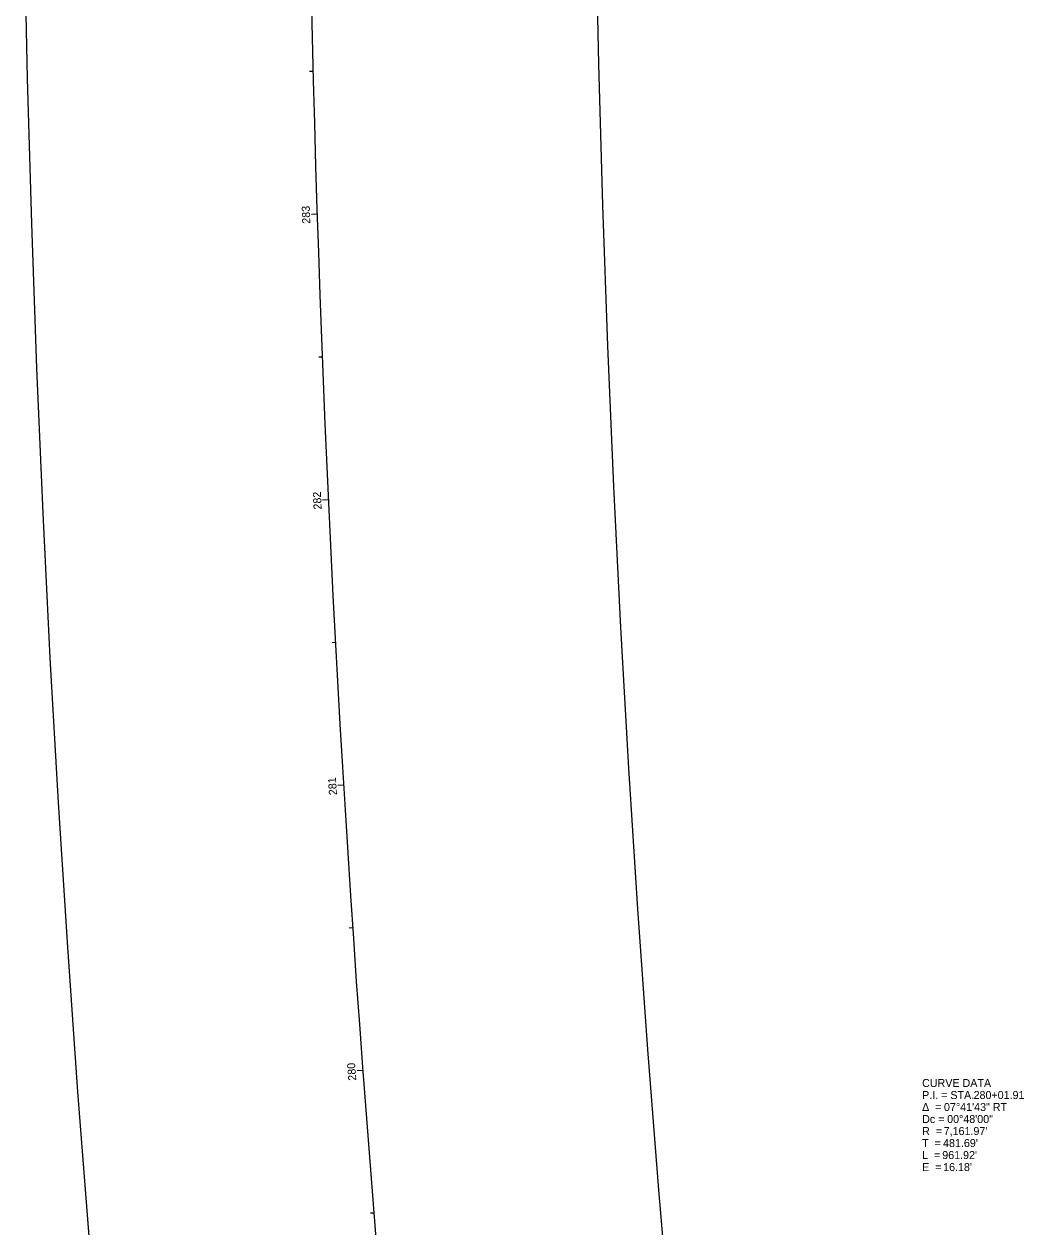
# Model space of a CAD drawing. Extents: x 1722814 to 1723176, y 329127 to 332105.
# Drawn here: x 1722817.9 to 1723167.7, y 330872.4 to 331293.2 of the extents above; entities that cross this region are included whole.
import ezdxf

# ---------------------------------------------------------------- set-up
doc = ezdxf.new("R2010")
doc.units = 0
for name, color, linetype in [('DR_P_Cells', 7, 'Continuous'), ('DR_X_Cells', 7, 'Continuous'), ('SV_X_Random_Point', 7, 'Continuous'), ('Wetland', 7, 'Continuous')]:
    doc.layers.add(name, color=color, linetype=linetype)

msp = doc.modelspace()

# ---------------------------------------------------------------- linework, layer by layer
at = {"layer": 'DR_P_Cells'}
for p, q in [((1722919, 331276.67), (1722917.8, 331276.64)), ((1722920.44, 331226.69), (1722918.44, 331226.63)), ((1722922.23, 331176.73), (1722921.03, 331176.68)), ((1722924.37, 331126.77), (1722922.37, 331126.68)), ((1722926.85, 331076.83), (1722925.65, 331076.77)), ((1722929.69, 331026.91), (1722927.69, 331026.79)), ((1722932.87, 330977.02), (1722931.67, 330976.94)), ((1722936.4, 330927.14), (1722934.4, 330926.99)), ((1722940.28, 330877.29), (1722939.08, 330877.19))]:
    msp.add_line(p, q, dxfattribs=at)
at = {"layer": 'DR_X_Cells'}
msp.add_lwpolyline([(1722844.89, 330818.67), (1723044.12, 330836.27), (1723039.95, 330885.4), (1723036.12, 330934.55), (1723032.64, 330983.73), (1723029.5, 331032.93), (1723026.71, 331082.15), (1723024.26, 331131.39), (1723022.15, 331180.65), (1723020.39, 331229.92), (1723018.97, 331279.2), (1723017.9, 331328.49), (1722817.93, 331324.83), (1722819.04, 331274.14), (1722820.49, 331223.47), (1722822.31, 331172.8), (1722824.47, 331122.15), (1722826.99, 331071.52), (1722829.87, 331020.9), (1722833.09, 330970.3), (1722836.67, 330919.73), (1722840.61, 330869.19)], close=True, dxfattribs=at)
at = {"layer": 'Wetland'}
msp.add_arc((1730078.68, 331457.77), 7161.97, 180.391728, 188.087121, dxfattribs=at)
msp.add_arc((1730078.68, 331457.77), 7161.97, 180.391728, 188.087121, dxfattribs=at)

# ---------------------------------------------------------------- texts
at = {"layer": 'DR_P_Cells'}
for s, rotation, p in [('283', 91.8489, (1722918.05, 331223.42)), ('282', 92.6489, (1722922.02, 331123.45)), ('281', 93.4489, (1722927.38, 331023.55)), ('280', 94.2489, (1722934.15, 330923.7))]:
    msp.add_text(s, height=2.8, rotation=rotation, dxfattribs=at).set_placement(p)
at = {"layer": 'SV_X_Random_Point'}
for s, p in [('CURVE DATA', (1723132.05, 330921.37)), ('P.I. = STA. ', (1723132.05, 330917.17)), ('280+01.91', (1723150.05, 330917.17)), ('Δ  = ', (1723132.05, 330912.97)), ('07°41\'43" RT', (1723139.7, 330912.97)), ('Dc = ', (1723132.05, 330908.77)), ('00°48\'00"', (1723140.8, 330908.77)), ('R  = ', (1723132.05, 330904.57)), ("7,161.97'", (1723139.59, 330904.57)), ('T  = ', (1723132.05, 330900.37)), ("481.69'", (1723139.37, 330900.37)), ('L  = ', (1723132.05, 330896.17)), ("961.92'", (1723139.09, 330896.17)), ('E  = ', (1723132.05, 330891.97)), ("16.18'", (1723139.4, 330891.97))]:
    msp.add_text(s, height=2.8, dxfattribs=at).set_placement(p)

doc.saveas('drawing.dxf')
